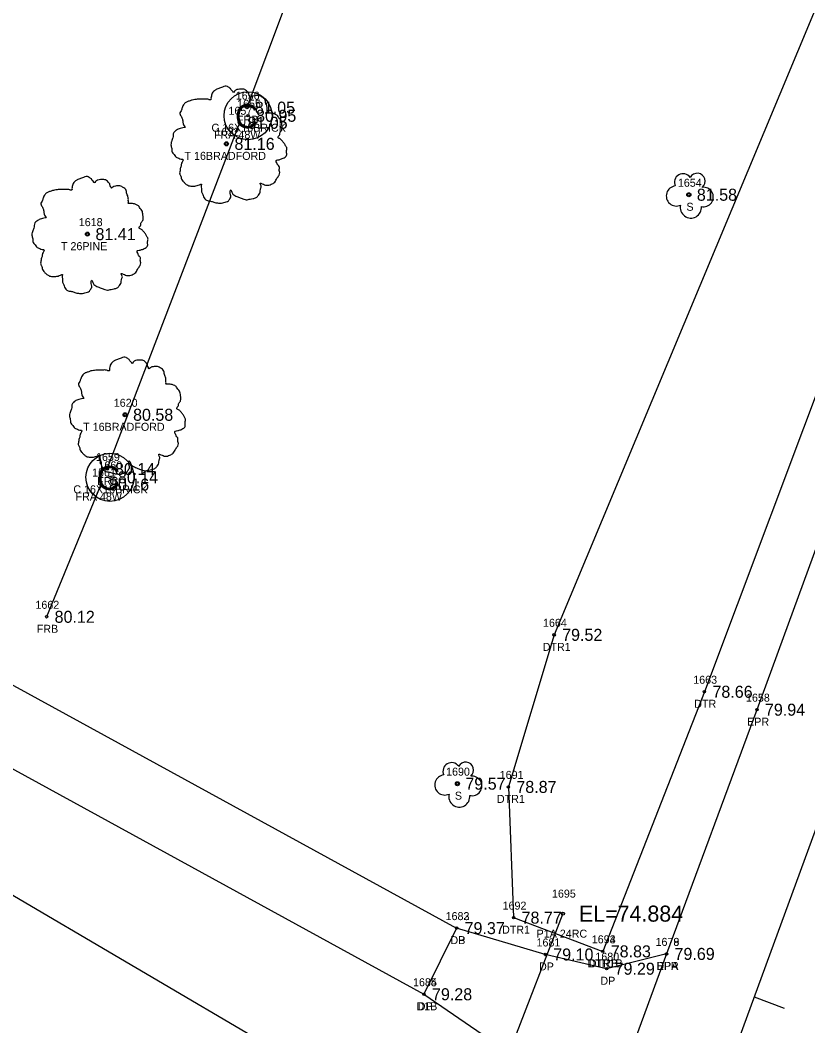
# Model space of a CAD drawing. Extents: x 2139392 to 2143384, y 505395 to 510520.
# Drawn here: x 2140971.8 to 2141070.2, y 509339.5 to 509465.1 of the extents above; entities that cross this region are included whole.
import ezdxf

# ---------------------------------------------------------------- set-up
doc = ezdxf.new("R2010")
doc.units = 0
for name, color, linetype in [('RD_EX_BldgApp', 7, 'Continuous'), ('RD_EX_BldgApp_txCode', 7, 'Continuous'), ('RD_EX_DR_Pipe', 7, 'Continuous'), ('RD_EX_DR_Pipe_txCode', 7, 'Continuous'), ('RD_EX_Driveway', 7, 'Continuous'), ('RD_EX_Driveway_txCode', 7, 'Continuous'), ('RD_EX_Fence_Other', 7, 'Continuous'), ('RD_EX_Fence_Other_txCode', 7, 'Continuous'), ('RD_EX_H2O', 7, 'Continuous'), ('RD_EX_H2O_txCode', 7, 'Continuous'), ('RD_EX_Road', 7, 'Continuous'), ('RD_EX_Road_txCode', 7, 'Continuous'), ('RD_EX_TX_BldgApp_ELEV', 7, 'Continuous'), ('RD_EX_TX_Driveway_ELEV', 7, 'Continuous'), ('RD_EX_TX_Fence_Other_ELEV', 7, 'Continuous'), ('RD_EX_TX_H2O_ELEV', 7, 'Continuous'), ('RD_EX_TX_Road_ELEV', 7, 'Continuous'), ('RD_EX_TX_VEG_ELEV', 7, 'Continuous'), ('RD_EX_VEG', 7, 'Continuous'), ('RD_EX_VEG_txCode', 7, 'Continuous'), ('RD_HC_Cl', 7, 'Continuous'), ('RD_HC_Data_Tic', 7, 'Continuous'), ('RD_SMD_Locator', 7, 'Continuous'), ('RD_TX_Pipe_ElevEX', 7, 'Continuous')]:
    doc.layers.add(name, color=color, linetype=linetype)

msp = doc.modelspace()

# ---------------------------------------------------------------- linework, layer by layer
at = {"layer": 'RD_EX_BldgApp'}
for centre in [(2141000.24, 509453.16), (2140982.98, 509408)]:
    msp.add_circle(centre, 3, dxfattribs=at)
at = {"layer": 'RD_EX_DR_Pipe'}
msp.add_line((2141039.58, 509353.51), (2141028.4, 509324.65), dxfattribs=at)
at = {"layer": 'RD_EX_Driveway'}
for points in [[(2140909.27, 509417.29), (2140964.34, 509385.59), (2141026.29, 509351.7)], [(2140903.55, 509409.36), (2140959.3, 509377.88), (2141022.22, 509343.44)], [(2141052.52, 509348.48), (2141045.04, 509346.63), (2141037.37, 509348.41), (2141026.29, 509351.7), (2141022.22, 509343.44), (2141033.2, 509335.93), (2141041.54, 509328.4), (2141043.48, 509323.88)]]:
    msp.add_lwpolyline(points, dxfattribs=at)
at = {"layer": 'RD_EX_Fence_Other'}
for p, q in [((2141017.31, 509500.01), (2141000.09, 509454.17)), ((2140999.16, 509452.28), (2140982.61, 509409.04)), ((2140981.86, 509407.1), (2140975.07, 509390.58))]:
    msp.add_line(p, q, dxfattribs=at)
at = {"layer": 'RD_EX_H2O'}
for points in [[(2141076.89, 509480.34), (2141038.48, 509388.33), (2141032.76, 509369.34), (2141033.41, 509353.01), (2141044.55, 509348.8)], [(2141076.89, 509480.34), (2141083.49, 509479.19), (2141090.32, 509475.51), (2141090.18, 509468.83), (2141057.26, 509381.22), (2141044.55, 509348.8)]]:
    msp.add_lwpolyline(points, dxfattribs=at)
at = {"layer": 'RD_EX_Road'}
msp.add_lwpolyline([(2141389.23, 510293.58), (2141374.66, 510243.58), (2141359.1, 510192.72), (2141341.17, 510140.58), (2141322.74, 510087.97), (2141303.61, 510035.12), (2141287.18, 509990.16), (2141276.99, 509962.02), (2141248.91, 509884.35), (2141213.37, 509787.47), (2141207.76, 509772.94), (2141199.35, 509749.36), (2141191.47, 509727.8), (2141175.93, 509686.04), (2141140.09, 509588.3), (2141106.08, 509494.11), (2141096.82, 509469.24), (2141063.82, 509378.98), (2141052.52, 509348.48), (2141043.48, 509323.88)], dxfattribs=at)
at = {"layer": 'RD_EX_VEG'}
msp.add_lwpolyline([(2140900.08, 509397.36), (2141021.29, 509326.2), (2140852.61, 508865.26), (2140689.34, 508413.46), (2140624.53, 508226.48), (2140606.41, 508171.78), (2140591.23, 508116.67), (2140558.82, 507962.77), (2140538.78, 507709.07), (2140410.61, 507724.88)], dxfattribs=at)
for centre, radius in [((2140997.54, 509449.65), 0.25), ((2140997.53, 509449.63), 0.0001), ((2141055.31, 509443.29), 0.25), ((2140980.17, 509438.37), 0.25), ((2140980.16, 509438.35), 0.0001), ((2140984.87, 509415.81), 0.25), ((2140984.86, 509415.79), 0.0001), ((2141026.39, 509369.74), 0.25)]:
    msp.add_circle(centre, radius, dxfattribs=at)
for centre, radius, start, end in [((2141054.59, 509444.84), 1.08, 34.9763, 204.756), ((2141056.36, 509444.99), 0.995, 308.7626, 152.0467), ((2141053.75, 509443.14), 1.26, 96.4518, 294.734), ((2141057.15, 509443.01), 1.22, 256.5667, 98.1046), ((2141055.56, 509441.7), 1.32, 166.8827, 5.7589), ((2141025.67, 509371.29), 1.08, 34.9763, 204.756), ((2141027.43, 509371.44), 0.995, 308.7626, 152.0467), ((2141024.82, 509369.58), 1.26, 96.4518, 294.734), ((2141028.23, 509369.46), 1.22, 256.5667, 98.1046), ((2141026.63, 509368.14), 1.32, 166.8827, 5.7589)]:
    msp.add_arc(centre, radius, start, end, dxfattribs=at)
for points in [[(2140997.67, 509456.82), (2140997.37, 509456.84), (2140997.05, 509456.74), (2140996.8, 509456.64), (2140996.57, 509456.57), (2140996.35, 509456.47), (2140996.05, 509456.29), (2140995.82, 509456.09), (2140995.7, 509455.84), (2140995.65, 509455.62), (2140995.6, 509455.34), (2140995.6, 509455.17), (2140995.47, 509455.14), (2140995.32, 509455.17), (2140995.07, 509455.24), (2140994.82, 509455.24), (2140994.57, 509455.24), (2140994.22, 509455.22), (2140993.87, 509455.22), (2140993.6, 509455.17), (2140993.27, 509455.12), (2140992.9, 509454.99), (2140992.55, 509454.87), (2140992.25, 509454.62), (2140992, 509454.14), (2140991.87, 509453.79), (2140991.72, 509453.54), (2140991.87, 509453.09), (2140992.05, 509452.74), (2140992.07, 509452.54), (2140992.15, 509452.12), (2140992.25, 509451.89), (2140992.37, 509451.69), (2140992.3, 509451.67), (2140991.92, 509451.62), (2140991.62, 509451.52), (2140991.2, 509451.3), (2140990.97, 509451.07), (2140990.87, 509450.75), (2140990.85, 509450.4), (2140990.75, 509450.2), (2140990.67, 509449.92), (2140990.65, 509449.85), (2140990.6, 509449.52), (2140990.7, 509449.07), (2140990.72, 509448.72), (2140990.85, 509448.5), (2140991, 509448.32), (2140991.17, 509448.07), (2140991.57, 509447.85), (2140991.9, 509447.75), (2140992.1, 509447.72), (2140991.92, 509447.22), (2140991.87, 509446.87), (2140991.75, 509446.47), (2140991.75, 509446.4), (2140991.7, 509445.92), (2140991.85, 509445.6), (2140991.92, 509445.22), (2140992.1, 509445), (2140992.37, 509444.7), (2140992.7, 509444.47), (2140993.2, 509444.35), (2140993.6, 509444.37), (2140994.17, 509444.55), (2140994.42, 509444.62), (2140994.4, 509444.45), (2140994.42, 509444.07), (2140994.42, 509443.65), (2140994.57, 509443.32), (2140994.67, 509443.05), (2140994.82, 509442.8), (2140995.15, 509442.57), (2140995.55, 509442.5), (2140995.97, 509442.35), (2140996.42, 509442.27), (2140996.92, 509442.25), (2140997.52, 509442.4), (2140997.8, 509442.52), (2140997.9, 509442.7), (2140998.1, 509443.07), (2140998.05, 509443.3), (2140998.07, 509443.9), (2140998.17, 509443.72), (2140998.35, 509443.37), (2140998.85, 509443.07), (2140999.25, 509442.9), (2140999.72, 509442.75), (2141000.02, 509442.67), (2141000.49, 509442.75), (2141000.87, 509442.82), (2141001.24, 509442.95), (2141001.54, 509443.22), (2141001.72, 509443.5), (2141001.77, 509443.77), (2141001.84, 509444.15), (2141001.89, 509444.32)], [(2141001.89, 509444.32), (2141001.82, 509444.5), (2141001.77, 509444.75), (2141001.84, 509444.72), (2141002.02, 509444.67), (2141002.29, 509444.55), (2141002.52, 509444.47), (2141002.84, 509444.5), (2141003.12, 509444.6), (2141003.57, 509444.87), (2141003.84, 509445.35), (2141004.12, 509445.75), (2141004.19, 509446.07), (2141004.14, 509446.3), (2141004.12, 509446.8), (2141003.92, 509447.05), (2141003.87, 509447.17), (2141003.77, 509447.57), (2141003.84, 509447.62), (2141004.12, 509447.67), (2141004.49, 509447.8), (2141004.77, 509447.92), (2141004.99, 509448.1), (2141005.07, 509448.32), (2141005.04, 509448.72), (2141005.09, 509449.12), (2141005.02, 509449.27), (2141004.92, 509449.42), (2141004.84, 509449.62), (2141004.69, 509449.77), (2141004.59, 509449.92), (2141004.49, 509450.02), (2141004.37, 509450.17), (2141004.19, 509450.3), (2141004.04, 509450.35), (2141003.99, 509450.5), (2141004.14, 509450.7), (2141004.19, 509450.8), (2141004.22, 509451.02), (2141004.44, 509451.37), (2141004.49, 509451.77), (2141004.44, 509452.19), (2141004.39, 509452.47), (2141004.24, 509452.74), (2141004.04, 509452.99), (2141003.92, 509453.17), (2141003.74, 509453.29), (2141003.42, 509453.42), (2141003.17, 509453.47), (2141002.82, 509453.47), (2141002.62, 509453.52), (2141002.64, 509453.57), (2141002.64, 509453.72), (2141002.64, 509453.99), (2141002.57, 509454.44), (2141002.42, 509454.94), (2141002.42, 509454.97), (2141002.32, 509455.22), (2141002.09, 509455.42), (2141001.92, 509455.52), (2141001.72, 509455.64), (2141001.47, 509455.67), (2141001.17, 509455.67), (2141000.89, 509455.62), (2141000.69, 509455.52), (2141000.52, 509455.39), (2141000.44, 509455.54), (2141000.34, 509455.84), (2141000.29, 509455.99), (2141000.14, 509456.17), (2140999.92, 509456.37), (2140999.47, 509456.49), (2140998.85, 509456.42), (2140998.55, 509456.22), (2140998.4, 509456.04), (2140998.35, 509456.17), (2140998.15, 509456.37), (2140998.05, 509456.54), (2140997.87, 509456.67), (2140997.72, 509456.77), (2140997.62, 509456.82)], [(2140980.31, 509445.53), (2140980.01, 509445.56), (2140979.68, 509445.46), (2140979.43, 509445.36), (2140979.21, 509445.28), (2140978.98, 509445.18), (2140978.68, 509445.01), (2140978.46, 509444.81), (2140978.33, 509444.56), (2140978.28, 509444.34), (2140978.23, 509444.06), (2140978.23, 509443.89), (2140978.11, 509443.86), (2140977.96, 509443.89), (2140977.71, 509443.96), (2140977.46, 509443.96), (2140977.21, 509443.96), (2140976.86, 509443.94), (2140976.51, 509443.94), (2140976.23, 509443.89), (2140975.91, 509443.84), (2140975.53, 509443.71), (2140975.18, 509443.59), (2140974.88, 509443.34), (2140974.63, 509442.86), (2140974.51, 509442.51), (2140974.36, 509442.26), (2140974.51, 509441.81), (2140974.68, 509441.46), (2140974.71, 509441.26), (2140974.78, 509440.84), (2140974.88, 509440.61), (2140975.01, 509440.41), (2140974.93, 509440.39), (2140974.56, 509440.34), (2140974.26, 509440.24), (2140973.83, 509440.01), (2140973.61, 509439.79), (2140973.51, 509439.46), (2140973.48, 509439.11), (2140973.38, 509438.91), (2140973.31, 509438.64), (2140973.28, 509438.56), (2140973.23, 509438.24), (2140973.33, 509437.79), (2140973.36, 509437.44), (2140973.48, 509437.21), (2140973.63, 509437.04), (2140973.81, 509436.79), (2140974.21, 509436.56), (2140974.53, 509436.46), (2140974.73, 509436.44), (2140974.56, 509435.94), (2140974.51, 509435.59), (2140974.38, 509435.19), (2140974.38, 509435.11), (2140974.33, 509434.64), (2140974.48, 509434.31), (2140974.56, 509433.94), (2140974.73, 509433.71), (2140975.01, 509433.41), (2140975.33, 509433.19), (2140975.83, 509433.07), (2140976.23, 509433.09), (2140976.81, 509433.26), (2140977.06, 509433.34), (2140977.03, 509433.17), (2140977.06, 509432.79), (2140977.06, 509432.37), (2140977.21, 509432.04), (2140977.31, 509431.77), (2140977.46, 509431.52), (2140977.78, 509431.29), (2140978.18, 509431.22), (2140978.61, 509431.07), (2140979.06, 509430.99), (2140979.56, 509430.97), (2140980.16, 509431.12), (2140980.43, 509431.24), (2140980.53, 509431.42), (2140980.73, 509431.79), (2140980.68, 509432.02), (2140980.71, 509432.62), (2140980.81, 509432.44), (2140980.98, 509432.09), (2140981.48, 509431.79), (2140981.88, 509431.62), (2140982.36, 509431.47), (2140982.66, 509431.39), (2140983.13, 509431.47), (2140983.51, 509431.54), (2140983.88, 509431.67), (2140984.18, 509431.94), (2140984.35, 509432.22), (2140984.4, 509432.49), (2140984.48, 509432.87), (2140984.53, 509433.04)], [(2140984.53, 509433.04), (2140984.45, 509433.22), (2140984.4, 509433.46), (2140984.48, 509433.44), (2140984.65, 509433.39), (2140984.93, 509433.26), (2140985.15, 509433.19), (2140985.48, 509433.22), (2140985.75, 509433.31), (2140986.2, 509433.59), (2140986.48, 509434.06), (2140986.75, 509434.46), (2140986.83, 509434.79), (2140986.78, 509435.01), (2140986.75, 509435.51), (2140986.55, 509435.76), (2140986.5, 509435.89), (2140986.4, 509436.29), (2140986.48, 509436.34), (2140986.75, 509436.39), (2140987.13, 509436.51), (2140987.4, 509436.64), (2140987.63, 509436.81), (2140987.7, 509437.04), (2140987.68, 509437.44), (2140987.73, 509437.84), (2140987.65, 509437.99), (2140987.55, 509438.14), (2140987.48, 509438.34), (2140987.33, 509438.49), (2140987.23, 509438.64), (2140987.13, 509438.74), (2140987, 509438.89), (2140986.83, 509439.01), (2140986.68, 509439.06), (2140986.63, 509439.21), (2140986.78, 509439.41), (2140986.83, 509439.51), (2140986.85, 509439.74), (2140987.08, 509440.09), (2140987.13, 509440.49), (2140987.08, 509440.91), (2140987.03, 509441.19), (2140986.88, 509441.46), (2140986.68, 509441.71), (2140986.55, 509441.89), (2140986.38, 509442.01), (2140986.05, 509442.14), (2140985.8, 509442.19), (2140985.45, 509442.19), (2140985.25, 509442.24), (2140985.28, 509442.29), (2140985.28, 509442.44), (2140985.28, 509442.71), (2140985.2, 509443.16), (2140985.05, 509443.66), (2140985.05, 509443.69), (2140984.95, 509443.94), (2140984.73, 509444.14), (2140984.55, 509444.24), (2140984.35, 509444.36), (2140984.1, 509444.39), (2140983.81, 509444.39), (2140983.53, 509444.34), (2140983.33, 509444.24), (2140983.16, 509444.11), (2140983.08, 509444.26), (2140982.98, 509444.56), (2140982.93, 509444.71), (2140982.78, 509444.88), (2140982.56, 509445.08), (2140982.11, 509445.21), (2140981.48, 509445.13), (2140981.18, 509444.93), (2140981.03, 509444.76), (2140980.98, 509444.88), (2140980.78, 509445.08), (2140980.68, 509445.26), (2140980.51, 509445.38), (2140980.36, 509445.48), (2140980.26, 509445.53)], [(2140985.01, 509422.98), (2140984.71, 509423), (2140984.38, 509422.9), (2140984.13, 509422.8), (2140983.91, 509422.73), (2140983.68, 509422.63), (2140983.38, 509422.45), (2140983.16, 509422.25), (2140983.03, 509422), (2140982.98, 509421.78), (2140982.93, 509421.5), (2140982.93, 509421.33), (2140982.81, 509421.3), (2140982.66, 509421.33), (2140982.41, 509421.4), (2140982.16, 509421.4), (2140981.91, 509421.4), (2140981.56, 509421.38), (2140981.21, 509421.38), (2140980.93, 509421.33), (2140980.61, 509421.28), (2140980.23, 509421.15), (2140979.88, 509421.03), (2140979.58, 509420.78), (2140979.33, 509420.3), (2140979.21, 509419.95), (2140979.06, 509419.7), (2140979.21, 509419.25), (2140979.38, 509418.9), (2140979.41, 509418.7), (2140979.48, 509418.28), (2140979.58, 509418.05), (2140979.71, 509417.85), (2140979.63, 509417.83), (2140979.26, 509417.78), (2140978.96, 509417.68), (2140978.53, 509417.45), (2140978.31, 509417.23), (2140978.21, 509416.9), (2140978.18, 509416.55), (2140978.08, 509416.35), (2140978.01, 509416.08), (2140977.98, 509416), (2140977.93, 509415.68), (2140978.03, 509415.23), (2140978.06, 509414.88), (2140978.18, 509414.65), (2140978.33, 509414.48), (2140978.51, 509414.23), (2140978.91, 509414), (2140979.23, 509413.9), (2140979.43, 509413.88), (2140979.26, 509413.38), (2140979.21, 509413.03), (2140979.08, 509412.63), (2140979.08, 509412.56), (2140979.03, 509412.08), (2140979.18, 509411.76), (2140979.26, 509411.38), (2140979.43, 509411.16), (2140979.71, 509410.86), (2140980.03, 509410.63), (2140980.53, 509410.51), (2140980.93, 509410.53), (2140981.51, 509410.71), (2140981.76, 509410.78), (2140981.73, 509410.61), (2140981.76, 509410.23), (2140981.76, 509409.81), (2140981.91, 509409.48), (2140982.01, 509409.21), (2140982.16, 509408.96), (2140982.48, 509408.73), (2140982.88, 509408.66), (2140983.31, 509408.51), (2140983.76, 509408.43), (2140984.26, 509408.41), (2140984.86, 509408.56), (2140985.13, 509408.68), (2140985.23, 509408.86), (2140985.43, 509409.23), (2140985.38, 509409.46), (2140985.4, 509410.06), (2140985.5, 509409.88), (2140985.68, 509409.53), (2140986.18, 509409.23), (2140986.58, 509409.06), (2140987.05, 509408.91), (2140987.35, 509408.83), (2140987.83, 509408.91), (2140988.2, 509408.98), (2140988.58, 509409.11), (2140988.88, 509409.38), (2140989.05, 509409.66), (2140989.1, 509409.93), (2140989.18, 509410.31), (2140989.23, 509410.48)], [(2140989.23, 509410.48), (2140989.15, 509410.66), (2140989.1, 509410.91), (2140989.18, 509410.88), (2140989.35, 509410.83), (2140989.63, 509410.71), (2140989.85, 509410.63), (2140990.18, 509410.66), (2140990.45, 509410.76), (2140990.9, 509411.03), (2140991.18, 509411.51), (2140991.45, 509411.91), (2140991.53, 509412.23), (2140991.48, 509412.46), (2140991.45, 509412.95), (2140991.25, 509413.2), (2140991.2, 509413.33), (2140991.1, 509413.73), (2140991.18, 509413.78), (2140991.45, 509413.83), (2140991.83, 509413.95), (2140992.1, 509414.08), (2140992.33, 509414.25), (2140992.4, 509414.48), (2140992.38, 509414.88), (2140992.43, 509415.28), (2140992.35, 509415.43), (2140992.25, 509415.58), (2140992.18, 509415.78), (2140992.03, 509415.93), (2140991.93, 509416.08), (2140991.83, 509416.18), (2140991.7, 509416.33), (2140991.53, 509416.45), (2140991.38, 509416.5), (2140991.33, 509416.65), (2140991.48, 509416.85), (2140991.53, 509416.95), (2140991.55, 509417.18), (2140991.78, 509417.53), (2140991.83, 509417.93), (2140991.78, 509418.35), (2140991.73, 509418.63), (2140991.58, 509418.9), (2140991.38, 509419.15), (2140991.25, 509419.33), (2140991.08, 509419.45), (2140990.75, 509419.58), (2140990.5, 509419.63), (2140990.15, 509419.63), (2140989.95, 509419.68), (2140989.98, 509419.73), (2140989.98, 509419.88), (2140989.98, 509420.15), (2140989.9, 509420.6), (2140989.75, 509421.1), (2140989.75, 509421.13), (2140989.65, 509421.38), (2140989.43, 509421.58), (2140989.25, 509421.68), (2140989.05, 509421.8), (2140988.8, 509421.83), (2140988.5, 509421.83), (2140988.23, 509421.78), (2140988.03, 509421.68), (2140987.85, 509421.55), (2140987.78, 509421.7), (2140987.68, 509422), (2140987.63, 509422.15), (2140987.48, 509422.33), (2140987.25, 509422.53), (2140986.8, 509422.65), (2140986.18, 509422.58), (2140985.88, 509422.38), (2140985.73, 509422.2), (2140985.68, 509422.33), (2140985.48, 509422.53), (2140985.38, 509422.7), (2140985.2, 509422.83), (2140985.06, 509422.93), (2140984.96, 509422.98)]]:
    msp.add_spline(points, degree=3, dxfattribs=at)
at = {"layer": 'RD_HC_Cl'}
msp.add_line((2141333.53, 510081.69), (2140670.51, 508268.37), dxfattribs=at)
at = {"layer": 'RD_HC_Data_Tic'}
msp.add_line((2141063.47, 509343.1), (2141067.23, 509341.72), dxfattribs=at)
at = {"layer": 'RD_SMD_Locator'}
for centre, radius in [((2141000.09, 509454.17), 0.15), ((2140999.16, 509452.28), 0.15), ((2141000.24, 509453.16), 0.15), ((2140997.54, 509449.65), 0.15), ((2141055.31, 509443.29), 0.15), ((2140980.17, 509438.37), 0.15), ((2140984.87, 509415.81), 0.15), ((2140982.61, 509409.04), 0.15), ((2140981.86, 509407.1), 0.15), ((2140982.98, 509408), 0.15), ((2140975.07, 509390.58), 0.15), ((2141038.48, 509388.33), 0.15), ((2141057.26, 509381.22), 0.15), ((2141063.82, 509378.98), 0.15), ((2141026.39, 509369.74), 0.15), ((2141032.76, 509369.34), 0.15), ((2141033.41, 509353.01), 0.15), ((2141039.58, 509353.51), 0.2), ((2141026.29, 509351.7), 0.15), ((2141026.29, 509351.7), 0.15), ((2141037.37, 509348.41), 0.15), ((2141044.55, 509348.8), 0.15), ((2141044.55, 509348.8), 0.15), ((2141052.52, 509348.48), 0.15), ((2141052.52, 509348.48), 0.15), ((2141045.04, 509346.63), 0.15), ((2141022.22, 509343.44), 0.15), ((2141022.22, 509343.44), 0.15)]:
    msp.add_circle(centre, radius, dxfattribs=at)

# ---------------------------------------------------------------- texts
at = {"layer": 'RD_EX_BldgApp'}
for p in [(2140998.61, 509451.6), (2140981.35, 509406.43)]:
    msp.add_text('C', height=3, dxfattribs=at).set_placement(p)
at = {"layer": 'RD_EX_BldgApp_txCode'}
for s, p in [('1655', (2140998.87, 509454.16)), ('C 16X16BRICK', (2140995.67, 509451.16)), ('1660', (2140981.54, 509409)), ('C 16X16BRICK', (2140978.41, 509406))]:
    msp.add_text(s, height=1, dxfattribs=at).set_placement(p)
at = {"layer": 'RD_EX_DR_Pipe_txCode'}
for s, p in [('1695', (2141038.21, 509355.51)), ('P1A 24RC', (2141036.29, 509350.51))]:
    msp.add_text(s, height=1, dxfattribs=at).set_placement(p)
at = {"layer": 'RD_EX_Driveway_txCode'}
for s, p in [('1682', (2141024.92, 509352.7)), ('1683', (2141024.92, 509352.7)), ('DP', (2141025.52, 509349.7)), ('DB', (2141025.52, 509349.7)), ('1681', (2141036.28, 509349.41)), ('1679', (2141051.15, 509349.48)), ('1680', (2141043.63, 509347.63)), ('DP', (2141036.59, 509346.41)), ('DPA', (2141051.25, 509346.48)), ('DP', (2141044.26, 509344.63)), ('1684', (2141020.85, 509344.44)), ('1685', (2141020.85, 509344.44)), ('D1B', (2141021.28, 509341.44)), ('DP', (2141021.44, 509341.44))]:
    msp.add_text(s, height=1, dxfattribs=at).set_placement(p)
at = {"layer": 'RD_EX_Fence_Other_txCode'}
for s, p in [('1656', (2140998.7, 509455.17)), ('1657', (2140997.79, 509453.28)), ('FRB', (2140998.86, 509452.17)), ('FRA 48W', (2140995.99, 509450.28)), ('1659', (2140981.24, 509410.04)), ('1661', (2140980.75, 509408.1)), ('FRB', (2140981.38, 509407.04)), ('FRA 48W', (2140978.69, 509405.1)), ('1662', (2140973.67, 509391.58)), ('FRB', (2140973.84, 509388.58))]:
    msp.add_text(s, height=1, dxfattribs=at).set_placement(p)
at = {"layer": 'RD_EX_H2O_txCode'}
for s, p in [('1664', (2141037.09, 509389.33)), ('DTR1', (2141037.05, 509386.33)), ('1663', (2141055.86, 509382.22)), ('DTR', (2141055.99, 509379.22)), ('1691', (2141031.68, 509370.34)), ('DTR1', (2141031.33, 509367.34)), ('1692', (2141032.04, 509354.01)), ('DTR1', (2141031.97, 509351.01)), ('1693', (2141043.18, 509349.8)), ('1694', (2141043.18, 509349.8)), ('DTR1B', (2141042.65, 509346.8)), ('DTRB', (2141042.81, 509346.8))]:
    msp.add_text(s, height=1, dxfattribs=at).set_placement(p)
at = {"layer": 'RD_EX_Road_txCode'}
for s, p in [('1658', (2141062.45, 509379.98)), ('EPR', (2141062.59, 509376.98)), ('1678', (2141051.15, 509349.48)), ('EPR', (2141051.29, 509346.48))]:
    msp.add_text(s, height=1, dxfattribs=at).set_placement(p)
at = {"layer": 'RD_EX_TX_BldgApp_ELEV'}
for s, p in [('80.95', (2141001.24, 509452.41)), ('80.14', (2140983.98, 509407.25))]:
    msp.add_text(s, height=1.5, dxfattribs=at).set_placement(p)
at = {"layer": 'RD_EX_TX_Driveway_ELEV'}
for s, p in [('79.37', (2141027.29, 509350.95)), ('79.37', (2141027.29, 509350.95)), ('79.10', (2141038.37, 509347.66)), ('79.69', (2141053.52, 509347.73)), ('79.29', (2141046.04, 509345.88)), ('79.28', (2141023.22, 509342.69)), ('79.28', (2141023.22, 509342.69))]:
    msp.add_text(s, height=1.5, dxfattribs=at).set_placement(p)
at = {"layer": 'RD_EX_TX_Fence_Other_ELEV'}
for s, p in [('81.05', (2141001.09, 509453.42)), ('81.05', (2141000.16, 509451.53)), ('80.14', (2140983.61, 509408.29)), ('80.16', (2140982.86, 509406.35)), ('80.12', (2140976.07, 509389.83))]:
    msp.add_text(s, height=1.5, dxfattribs=at).set_placement(p)
at = {"layer": 'RD_EX_TX_H2O_ELEV'}
for s, p in [('79.52', (2141039.48, 509387.58)), ('78.66', (2141058.26, 509380.47)), ('78.87', (2141033.76, 509368.59)), ('78.77', (2141034.41, 509352.26)), ('78.83', (2141045.55, 509348.05)), ('78.83', (2141045.55, 509348.05))]:
    msp.add_text(s, height=1.5, dxfattribs=at).set_placement(p)
at = {"layer": 'RD_EX_TX_Road_ELEV'}
for s, p in [('79.94', (2141064.82, 509378.23)), ('79.69', (2141053.52, 509347.73))]:
    msp.add_text(s, height=1.5, dxfattribs=at).set_placement(p)
at = {"layer": 'RD_EX_TX_VEG_ELEV'}
for s, p in [('81.16', (2140998.54, 509448.9)), ('81.58', (2141056.31, 509442.54)), ('81.41', (2140981.17, 509437.62)), ('80.58', (2140985.87, 509415.06)), ('79.57', (2141027.39, 509368.99))]:
    msp.add_text(s, height=1.5, dxfattribs=at).set_placement(p)
at = {"layer": 'RD_EX_VEG_txCode'}
for s, p in [('1622', (2140996.17, 509450.65)), ('T 16BRADFORD', (2140992.3, 509447.65)), ('1654', (2141053.94, 509444.29)), ('S', (2141055.01, 509441.29)), ('1618', (2140979.09, 509439.37)), ('T 26PINE', (2140976.86, 509436.37)), ('1620', (2140983.46, 509416.81)), ('T 16BRADFORD', (2140979.64, 509413.81)), ('1690', (2141024.98, 509370.74)), ('S', (2141026.08, 509367.74))]:
    msp.add_text(s, height=1, dxfattribs=at).set_placement(p)
at = {"layer": 'RD_TX_Pipe_ElevEX'}
msp.add_text('EL=74.884', height=2, dxfattribs=at).set_placement((2141041.58, 509352.51))

doc.saveas('drawing.dxf')
